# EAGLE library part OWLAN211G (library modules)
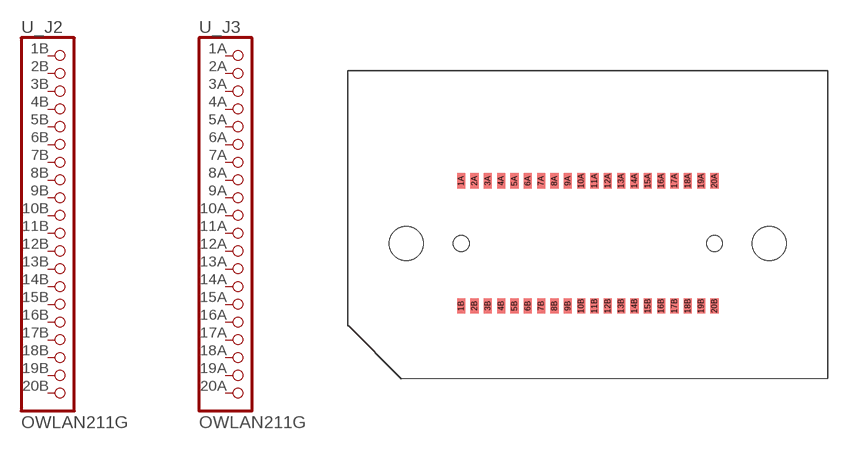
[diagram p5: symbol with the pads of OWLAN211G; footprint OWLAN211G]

Designator prefix -; gates _J2=PINHD20 _J3=PINHD20

## OWLAN211G  [OWLAN211G]
1A  _J3:1  pas
1B  _J2:1  pas
2A  _J3:2  pas
2B  _J2:2  pas
3A  _J3:3  pas
3B  _J2:3  pas
4A  _J3:4  pas
4B  _J2:4  pas
5A  _J3:5  pas
5B  _J2:5  pas
6A  _J3:6  pas
6B  _J2:6  pas
7A  _J3:7  pas
7B  _J2:7  pas
8A  _J3:8  pas
8B  _J2:8  pas
9A  _J3:9  pas
9B  _J2:9  pas
10A  _J3:10  pas
10B  _J2:10  pas
11A  _J3:11  pas
11B  _J2:11  pas
12A  _J3:12  pas
12B  _J2:12  pas
13A  _J3:13  pas
13B  _J2:13  pas
14A  _J3:14  pas
14B  _J2:14  pas
15A  _J3:15  pas
15B  _J2:15  pas
16A  _J3:16  pas
16B  _J2:16  pas
17A  _J3:17  pas
17B  _J2:17  pas
18A  _J3:18  pas
18B  _J2:18  pas
19A  _J3:19  pas
19B  _J2:19  pas
20A  _J3:20  pas
20B  _J2:20  pas

## Footprint OWLAN211G (pad centres in mm)
ConnectBlue OWLAN211g i/x cB-0909 Drawn by: CT
smd 0.61 x 1.13: 1A -9.5,4.695; 1B -9.5,-4.695; 2A -8.5,4.695; 2B -8.5,-4.695; 3A -7.5,4.695; 3B -7.5,-4.695; 4A -6.5,4.695; 4B -6.5,-4.695; 5A -5.5,4.695; 5B -5.5,-4.695; 6A -4.5,4.695; 6B -4.5,-4.695; 7A -3.5,4.695; 7B -3.5,-4.695; 8A -2.5,4.695; 8B -2.5,-4.695; 9A -1.5,4.695; 9B -1.5,-4.695; 10A -0.5,4.695; 10B -0.5,-4.695; 11A 0.5,4.695; 11B 0.5,-4.695; 12A 1.5,4.695; 12B 1.5,-4.695; 13A 2.5,4.695; 13B 2.5,-4.695; 14A 3.5,4.695; 14B 3.5,-4.695; 15A 4.5,4.695; 15B 4.5,-4.695; 16A 5.5,4.695; 16B 5.5,-4.695; 17A 6.5,4.695; 17B 6.5,-4.695; 18A 7.5,4.695; 18B 7.5,-4.695; 19A 8.5,4.695; 19B 8.5,-4.695; 20A 9.5,4.695; 20B 9.5,-4.695
hole 2.54 at -13.62,0
hole 2.54 at 13.62,0
hole 1.19 at -9.5,0
hole 1.19 at 9.5,0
